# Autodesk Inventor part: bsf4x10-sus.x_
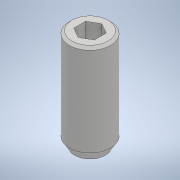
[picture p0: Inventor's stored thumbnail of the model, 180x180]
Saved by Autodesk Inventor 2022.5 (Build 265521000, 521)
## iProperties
Created: 2020-01
Part Number: bsf4x10-sus.x_
Material: 一般
Document SubType Name: Modeling
Designer: ImaoCorp
Density: 1 g/cm^3
Appearance: 既定
Sending System: SOLIDWORKS 2018-2018316
MC: AMD64
MC_MODEL: Intel64 Family 6 Model 60 Stepping 3, GenuineIntel
OS: Windows_NT
FRU: Parasolid Version 30.0, build 310,  6- 8-2018
FORMAT: text
GUISE: transmit
KEY: bsf4x10-sus
FILE: bsf4x10-sus.x_t
DATE: Thu Jan 23 16:48:58 2020
Author: ImaoCorp
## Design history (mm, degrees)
feature "Base1"
node "ソリッド1"
